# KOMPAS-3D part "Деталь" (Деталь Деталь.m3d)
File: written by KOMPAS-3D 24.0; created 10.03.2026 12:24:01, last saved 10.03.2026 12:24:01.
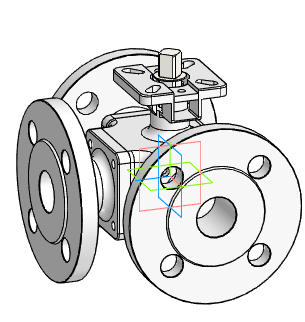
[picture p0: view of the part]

Document properties: Автор: R2D2; Полное имя файла: E:\Работа\Зайцев\BV3232P(4pc)-FP-3WL-F-ISO-H Кран шаровой DN.ru Ду15-100 Ру16\DN32\исходные материалы\Деталь Деталь.m3d

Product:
- Body: Твердое тело1  | qty 1
- Part/product: Деталь
    additional columns: Типовые

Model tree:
1. Твердое тело1  (labels: Твердое тело1)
